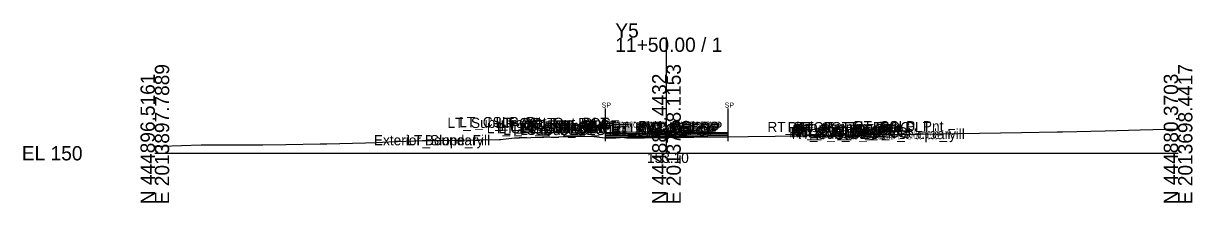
# Model space of a CAD drawing. Extents: x -26 to 203, y -10 to 4517.
# Drawn here: x -25.7 to 202.8, y 2990.3 to 3025.5 of the extents above; entities that cross this region are included whole.
import ezdxf

# ---------------------------------------------------------------- set-up
doc = ezdxf.new("R2010")
doc.units = 0
for name, color, linetype in [('Default', 7, 'Continuous'), ('Exist Cross Section Cell', 7, 'Continuous'), ('Exist XS Center Line Elevation Label', 7, 'Continuous'), ('Exist XS Ground Line', 7, 'Continuous'), ('Prop CMT Pvmt Course 1', 7, 'Continuous'), ('Prop CMT Pvmt Course 2', 7, 'Continuous'), ('Prop CMT Pvmt Course 3', 7, 'Continuous'), ('Prop CMT Pvmt Surface', 7, 'Continuous'), ('Prop CMT Shear Line', 7, 'Continuous'), ('Prop CMT Subgrade Earthwork', 7, 'Continuous'), ('Prop XS Earthwork Shape', 7, 'Continuous'), ('Prop XS SE Text', 7, 'Continuous'), ('Scratch_Level_0', 7, 'Continuous')]:
    doc.layers.add(name, color=color, linetype=linetype)

msp = doc.modelspace()

# ---------------------------------------------------------------- linework, layer by layer
at = {"layer": 'Exist Cross Section Cell'}
for p, q in [((100, 3000), (100, 3022.67)), ((0, 3000), (100, 3000)), ((100, 3000), (200, 3000))]:
    msp.add_line(p, q, dxfattribs=at)
at = {"layer": 'Exist XS Ground Line'}
msp.add_lwpolyline([(0, 3001.4), (1.39, 3001.4), (9.08, 3001.66), (17.19, 3001.62), (21.1, 3001.63), (25.62, 3001.69), (32.29, 3001.83), (33.65, 3001.87), (41.17, 3002.05), (43.2, 3002.13), (47.05, 3002.27), (47.4, 3002.28), (52.32, 3002.48), (55.96, 3002.51), (62.91, 3002.63), (67.27, 3002.72), (67.59, 3002.72), (70.3, 3003), (71.28, 3003.05), (75.69, 3003.17), (85.21, 3003.33), (88.08, 3003.02), (88.46, 3002.98), (90.12, 3002.99), (90.92, 3003.08), (91.23, 3003.15), (91.72, 3003.09), (92.21, 3003.02), (95.73, 3003.05), (96.92, 3003.06), (98.46, 3003.08), (100, 3003.1), (126.58, 3003.42), (142.95, 3003.66), (146, 3003.7), (152.95, 3003.8), (169.38, 3004.08), (176.38, 3004.18), (177.09, 3004.2), (177.41, 3004.2), (185.76, 3004.41), (192.6, 3004.59), (200, 3004.78)], dxfattribs=at)
at = {"layer": 'Prop CMT Pvmt Course 1'}
for points in [[(100, 3004.23), (88, 3003.99)], [(88, 3003.74), (100, 3003.98)], [(100, 3003.98), (100, 3004.23)], [(100, 3004.23), (112, 3004.05)], [(100, 3003.98), (100, 3004.23)], [(112, 3003.8), (100, 3003.98)]]:
    msp.add_lwpolyline(points, dxfattribs=at)
msp.add_lwpolyline([(100, 3003.98), (100, 3004.11), (100, 3004.11), (100, 3003.98)], close=True, dxfattribs=at)
msp.add_lwpolyline([(100, 3003.98), (100, 3004.11), (100, 3004.11), (100, 3003.98)], close=True, dxfattribs=at)
at = {"layer": 'Prop CMT Pvmt Course 2'}
for points in [[(100, 3003.98), (88, 3003.74)], [(88, 3003.41), (100, 3003.65)], [(100, 3003.65), (100, 3003.98)], [(100, 3003.65), (100, 3003.98)], [(100, 3003.98), (112, 3003.8)], [(112, 3003.47), (100, 3003.65)]]:
    msp.add_lwpolyline(points, dxfattribs=at)
at = {"layer": 'Prop CMT Pvmt Course 3'}
for points in [[(100, 3003.65), (88, 3003.41)], [(88, 3003.08), (100, 3003.32)], [(100, 3003.32), (100, 3003.65)], [(100, 3003.65), (112, 3003.47)], [(100, 3003.32), (100, 3003.65)], [(112, 3003.14), (100, 3003.32)]]:
    msp.add_lwpolyline(points, dxfattribs=at)
at = {"layer": 'Prop CMT Pvmt Surface'}
for points in [[(100, 3004.23), (88, 3003.99)], [(100, 3004.23), (112, 3004.05)]]:
    msp.add_lwpolyline(points, dxfattribs=at)
at = {"layer": 'Prop CMT Shear Line'}
for p, q in [((88, 3008.8), (88, 3002.34)), ((112, 3008.8), (112, 3002.34))]:
    msp.add_line(p, q, dxfattribs=at)
at = {"layer": 'Prop CMT Subgrade Earthwork'}
for p, q in [((88, 3003.08), (88, 3003.03)), ((112, 3003.24), (112, 3003.14))]:
    msp.add_line(p, q, dxfattribs=at)
for points in [[(100, 3003.32), (88, 3003.08)], [(100, 3003.32), (112, 3003.14)]]:
    msp.add_lwpolyline(points, dxfattribs=at)
at = {"layer": 'Prop XS Earthwork Shape'}
for points in [[(90.12, 3002.99), (90.92, 3003.08), (91.19, 3003.14), (88, 3003.08), (88, 3003.03), (88.08, 3003.02), (88.46, 3002.98)], [(91.29, 3003.14), (91.19, 3003.14), (91.23, 3003.15)], [(100, 3003.32), (91.29, 3003.14), (91.72, 3003.09), (92.21, 3003.02), (95.73, 3003.05), (96.92, 3003.06), (98.46, 3003.08), (100, 3003.1), (108.08, 3003.2)], [(108.08, 3003.2), (112, 3003.24), (112, 3003.14)]]:
    msp.add_lwpolyline(points, close=True, dxfattribs=at)

# ---------------------------------------------------------------- texts
at = {"layer": 'Default'}
msp.add_text('-', height=0.0001, dxfattribs=at).set_placement((0, 3000))
at = {"layer": 'Exist Cross Section Cell'}
for s, p in [('Y5', (90, 3022.67)), ('11+50.00 / 1', (90, 3019.87)), ('EL 150', (-26, 2998.6))]:
    msp.add_text(s, height=2.8, dxfattribs=at).set_placement(p)
for s, p in [('E 2013897.7889', (2.8, 2990)), ('E 2013798.1153', (102.8, 2990)), ('E 2013698.4417', (202.8, 2990)), ('N 444896.5161', (0, 2990)), ('N 444888.4432', (100, 2990)), ('N 444880.3703', (200, 2990))]:
    msp.add_text(s, height=2.8, rotation=90, dxfattribs=at).set_placement(p)
at = {"layer": 'Exist XS Center Line Elevation Label'}
msp.add_text('153.10', height=2, dxfattribs=at).set_placement((96.19, 2998.1))
at = {"layer": 'Prop XS SE Text'}
for s, rotation, p in [('SP', 360, (87.33, 3008.94)), ('SP', 360, (111.37, 3008.94)), ('0.020', 1.1458, (92.35, 3005)), ('0.015', 359.1406, (105.38, 3005.08))]:
    msp.add_text(s, height=1, rotation=rotation, dxfattribs=at).set_placement(p)
at = {"layer": 'Scratch_Level_0'}
for s, p in [('LT_Sub_Trench_Out_DLT', (57.18, 3004.96)), ('LT_CSLP_Pnt', (59.49, 3005.11)), ('LT_CG1_Shelf_Out', (64.87, 3003.92)), ('LT_CG_Top_Face', (66.58, 3004.92)), ('LT_CG_Top_BOC', (67.1, 3004.92)), ('LT_CG_Bot_BOC', (67.13, 3003.92)), ('LT_CG_Top_Gut', (67.55, 3004.42)), ('LT_Sub_OEOP', (68.1, 3003.59)), ('LT_CG_Bot_IE', (71.23, 3003.9)), ('LT_Sub_OEOT', (71.4, 3003.56)), ('LT_PV2_OEOT', (71.49, 3004.23)), ('LT_PV3_OEOT', (71.49, 3003.9)), ('LT_PV1_OEOT', (72.06, 3004.48)), ('RT_Sub_OEEOP', (89.17, 3003.42)), ('LT_Sub_OEEOP', (89.21, 3003.42)), ('RT_PV2_OEEOP', (89.26, 3004.09)), ('RT_PV3_OEEOP', (89.26, 3003.75)), ('LT_PV2_OEEOP', (89.31, 3004.09)), ('LT_PV3_OEEOP', (89.31, 3003.75)), ('RT_PV1_OEEOP', (89.83, 3004.21)), ('LT_PV1_OEEOP', (89.87, 3004.21)), ('RT_PV2_IEEOP', (89.91, 3004.09)), ('LT_PV2_IEEOP', (89.95, 3004.09)), ('RT_PV1_IEEOP', (90.47, 3004.21)), ('LT_PV1_IEEOP', (90.52, 3004.21)), ('PV2_PGL', (93.91, 3004.09)), ('PV1_PGL', (94.47, 3004.34)), ('RT_Sub_Trench_Out_DLT', (119.73, 3004.15)), ('RT_CG_Top_Face', (123.68, 3004.11)), ('RT_PV2_OEOT', (124.59, 3003.47)), ('RT_CG_Top_Gut', (124.65, 3003.61)), ('RT_PV1_OEOT', (125.16, 3003.72)), ('RT_CG_Top_BOC', (125.2, 3004.11)), ('RT_CSLP_Pnt', (136.59, 3004.3)), ('Exterior Boundary', (42.81, 3001.56)), ('LT_Slope_Fill', (49.18, 3001.56)), ('RT_CG1_Shelf_Out', (123.97, 3003.09)), ('RT_CG_Bot_IE', (124.33, 3003.14)), ('RT_Sub_OEOT', (124.49, 3002.81)), ('RT_PV3_OEOT', (124.59, 3003.14)), ('RT_CG_Bot_BOC', (125.23, 3003.1)), ('RT_Sub_OEOP', (127.87, 3002.75)), ('Exterior Boundary', (135.18, 3002.77)), ('RT_Slope_Fill', (141.51, 3002.77))]:
    msp.add_text(s, height=2, dxfattribs=at).set_placement(p)

doc.saveas('drawing.dxf')
